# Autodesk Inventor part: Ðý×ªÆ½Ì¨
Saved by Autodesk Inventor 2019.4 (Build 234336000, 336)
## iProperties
Created: 2020-05
Part Number: Ðý×ªÆ½Ì¨
Material: Generic
Document SubType Name: Modeling
Designer: Administrator
Density: 1 g/cm^3
Appearance: Default
Title: Ðý×ªÆ½Ì¨
Author: Administrator
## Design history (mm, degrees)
feature "Body1"
body "Solid1"
